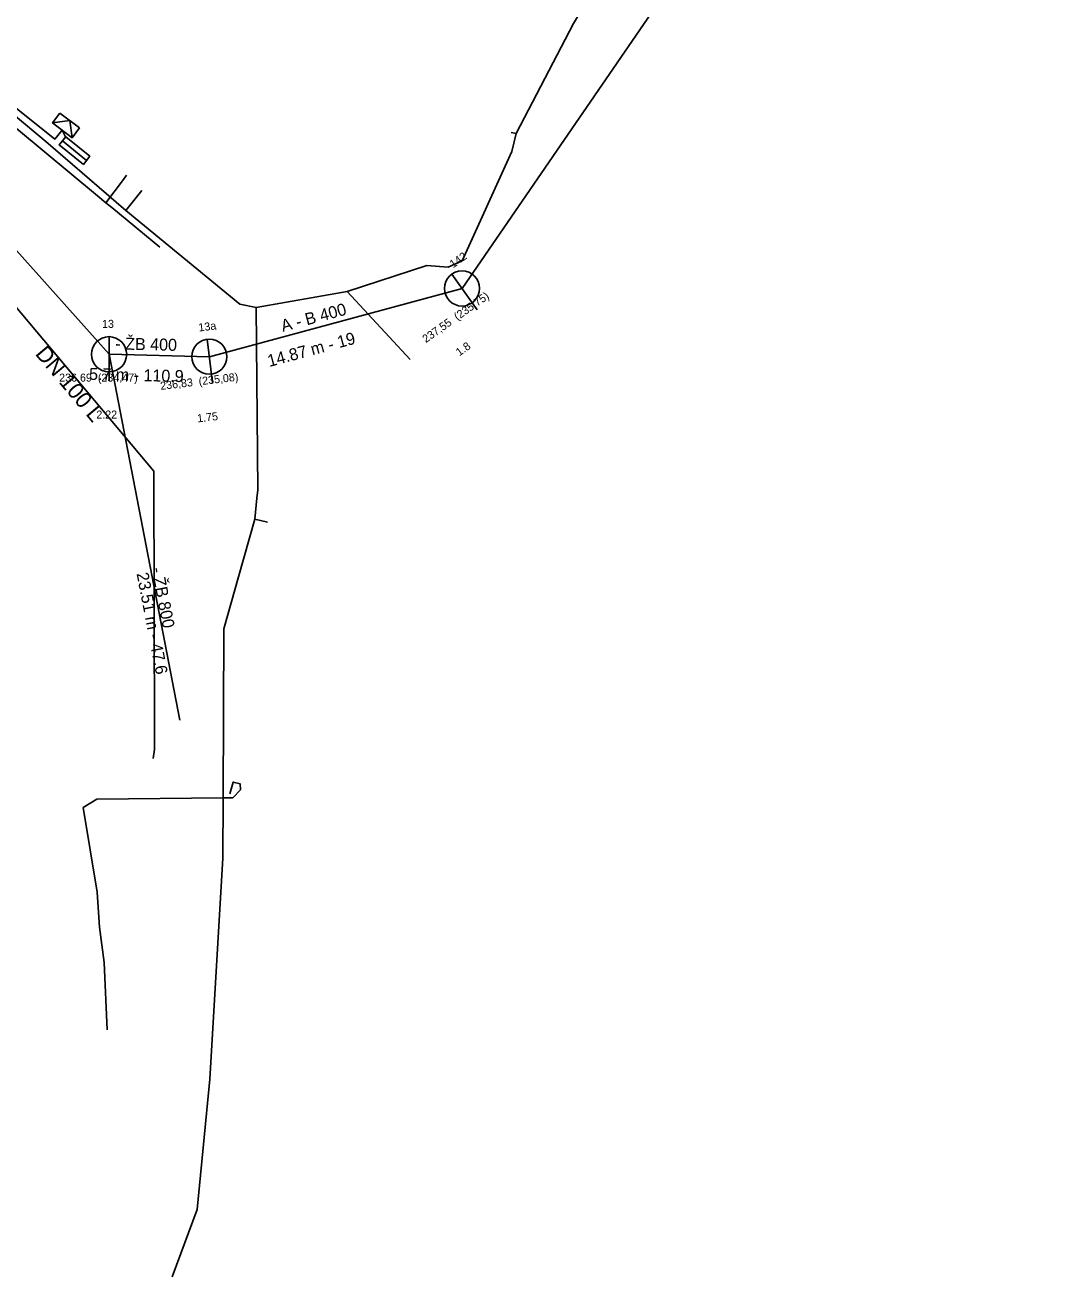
# Model space of a CAD drawing. Extents: x -600636 to -600148, y -1203980 to -1203569.
# Drawn here: x -600381.7 to -600322.7, y -1203980.3 to -1203909.2 of the extents above; entities that cross this region are included whole.
import ezdxf

# ---------------------------------------------------------------- set-up
doc = ezdxf.new("R2010")
doc.units = 0
for name, color, linetype in [('Cetin NN přípojka', 7, 'Continuous'), ('Cetin zam průběh', 7, 'Continuous'), ('EON podzemní NN', 7, 'Continuous'), ('GasNet STL', 7, 'Continuous'), ('Implicitní', 7, 'Continuous'), ('VaK Břeclav_kanalizace', 7, 'Continuous'), ('VaK Břeclav_kanalizace_popis', 7, 'Continuous'), ('Vak Břeclav_vodovod', 7, 'Continuous'), ('Vak Břeclav_vodovod_popis', 7, 'Continuous'), ('Vrstva 9', 7, 'Continuous')]:
    doc.layers.add(name, color=color, linetype=linetype)

# ---------------------------------------------------------------- blocks, each defined once
blk = doc.blocks.new('NN630')
at = {"layer": 'Vrstva 9'}
for points in [[(-0.003, -0.7), (-0.703, 0)], [(-0.703, -0.7), (-0.703, 0), (0.697, 0), (0.697, -0.7)], [(-0.703, -0.7), (0.697, -0.7)], [(-0.003, -0.7), (0.697, 0)]]:
    blk.add_lwpolyline(points, dxfattribs=at)
blk = doc.blocks.new('MoSymbol 2')
at = {"layer": 'Implicitní'}
blk.add_line((0, 0.0005), (0, -0.00075), dxfattribs=at)
blk.add_circle((0, 0), 0.0005, dxfattribs=at)

msp = doc.modelspace()

# ---------------------------------------------------------------- linework, layer by layer
at = {"layer": 'Cetin NN přípojka'}
for points in [[(-600375.93, -1203919.71), (-600380.48, -1203915.79), (-600384.28, -1203912.62)], [(-600369.45, -1203925.03), (-600375.93, -1203919.71)], [(-600368.52, -1203925.23), (-600369.45, -1203925.03)], [(-600368.6, -1203937.26), (-600368.48, -1203936.06), (-600368.43, -1203935.58), (-600368.52, -1203925.23)], [(-600373.29, -1203980.33), (-600371.87, -1203976.49), (-600371.16, -1203969.09), (-600370.42, -1203956.52), (-600370.4, -1203953.1), (-600370.36, -1203943.48), (-600369.52, -1203940.54), (-600368.6, -1203937.26)]]:
    msp.add_lwpolyline(points, dxfattribs=at)
at = {"layer": 'Cetin zam průběh'}
for points in [[(-600335.63, -1203887.95), (-600339.37, -1203893.05), (-600341.59, -1203896.64), (-600342.53, -1203897.34), (-600343.84, -1203899.03), (-600344.48, -1203900.27), (-600348.64, -1203906.02), (-600350.48, -1203909.08), (-600353.75, -1203915.34)], [(-600375.93, -1203919.71), (-600380.48, -1203915.79), (-600384.28, -1203912.62)], [(-600353.75, -1203915.34), (-600353.99, -1203916.35), (-600356.82, -1203922.57), (-600357.6, -1203922.94), (-600358.81, -1203922.84), (-600363.34, -1203924.32)], [(-600354.03, -1203915.28), (-600353.75, -1203915.34)], [(-600375.93, -1203919.71), (-600375.01, -1203918.57)], [(-600369.45, -1203925.03), (-600375.93, -1203919.71)], [(-600368.52, -1203925.23), (-600363.34, -1203924.32)], [(-600359.76, -1203928.18), (-600363.34, -1203924.32)], [(-600368.52, -1203925.23), (-600369.45, -1203925.03)], [(-600368.6, -1203937.26), (-600368.48, -1203936.06), (-600368.43, -1203935.58), (-600368.52, -1203925.23)], [(-600368.43, -1203935.58), (-600368.52, -1203925.23)], [(-600373.29, -1203980.33), (-600371.87, -1203976.49), (-600371.16, -1203969.09), (-600370.42, -1203956.52), (-600370.4, -1203953.1), (-600370.36, -1203943.48), (-600369.52, -1203940.54), (-600368.6, -1203937.26)], [(-600368.6, -1203937.26), (-600367.88, -1203937.42)], [(-600370.01, -1203952.86), (-600369.82, -1203952.2), (-600369.43, -1203952.29), (-600369.41, -1203952.64), (-600369.85, -1203953.09), (-600370.4, -1203953.1), (-600377.57, -1203953.18), (-600378.36, -1203953.65), (-600377.55, -1203958.46), (-600377.43, -1203960.44), (-600377.16, -1203962.46), (-600376.99, -1203966.29)], [(-600378.36, -1203953.65), (-600377.57, -1203953.18), (-600370.4, -1203953.1), (-600369.85, -1203953.09), (-600369.41, -1203952.64)]]:
    msp.add_lwpolyline(points, dxfattribs=at)
at = {"layer": 'EON podzemní NN'}
msp.add_lwpolyline([(-600378.16, -1203916.863), (-600379.522, -1203915.745), (-600379.349, -1203915.528), (-600379.54, -1203915.15), (-600379.957, -1203915.651), (-600387.504, -1203909.637), (-600390.807, -1203907.047), (-600391.062, -1203906.995), (-600393.313, -1203904.332), (-600393.34, -1203904.193), (-600393.41, -1203902.313), (-600393.3, -1203900.631), (-600393.268, -1203900.631)], dxfattribs=at)
msp.add_lwpolyline([(-600378.34, -1203917.104), (-600379.712, -1203915.977), (-600379.332, -1203915.513), (-600377.98, -1203916.623)], close=True, dxfattribs=at)
at = {"layer": 'GasNet STL'}
for points in [[(-600382.26, -1203914.94), (-600382.14, -1203915.04), (-600377.54, -1203918.87), (-600377.06, -1203919.27)], [(-600377.06, -1203919.27), (-600376.056, -1203917.943), (-600375.88, -1203917.71)], [(-600377.06, -1203919.27), (-600376.73, -1203919.54), (-600373.992, -1203921.797)]]:
    msp.add_lwpolyline(points, dxfattribs=at)
at = {"layer": 'VaK Břeclav_kanalizace'}
for p, q in [((-600322.72, -1203874.5), (-600356.82, -1203924.14)), ((-600376.879, -1203927.881), (-600392.69, -1203910.19)), ((-600356.82, -1203924.14), (-600371.18, -1203928.02)), ((-600372.86, -1203948.688), (-600376.879, -1203927.881)), ((-600371.18, -1203928.02), (-600376.879, -1203927.881))]:
    msp.add_line(p, q, dxfattribs=at)
at = {"layer": 'Vak Břeclav_vodovod'}
for p in [(-600374.301, -1203949.917), (-600374.371, -1203950.866)]:
    msp.add_line(p, (-600374.3, -1203950.35), dxfattribs=at)
msp.add_lwpolyline([(-600391.91, -1203913.607), (-600374.345, -1203934.519), (-600374.301, -1203949.917)], dxfattribs=at)

# ---------------------------------------------------------------- block references
at = {"layer": 'EON podzemní NN', "rotation": 142.71324171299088}
msp.add_blockref('NN630', (-600379.54, -1203915.15), dxfattribs=at)
at = {"layer": 'VaK Břeclav_kanalizace'}
for p, xscale, yscale, rotation in [((-600356.82, -1203924.14), 1999.750031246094, 1999.7500312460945, 35.31651185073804), ((-600371.18, -1203928.02), 1999.7500312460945, 1999.7500312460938, 6.841182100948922)]:
    msp.add_blockref('MoSymbol 2', p, dxfattribs=dict(at, xscale=xscale, yscale=yscale, rotation=rotation))
at = {"layer": 'VaK Břeclav_kanalizace', "xscale": 1999.750031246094, "yscale": 1999.750031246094}
msp.add_blockref('MoSymbol 2', (-600376.879, -1203927.881), dxfattribs=at)

# ---------------------------------------------------------------- texts
at = {"layer": 'VaK Břeclav_kanalizace_popis'}
for s, height, rotation, p in [('142', 0.4549, 35.31651, (-600357.324, -1203922.997)), ('237,55  (235,75)', 0.45494, 35.31651, (-600358.873, -1203927.252)), ('A - B 400', 0.6824, 15.11999, (-600367.007, -1203926.61)), ('13a', 0.4549, 6.84118, (-600371.772, -1203926.591)), ('- ŽB 400', 0.6824, 358.59872, (-600376.527, -1203927.607)), ('14.87 m - 19', 0.68241, 15.11999, (-600367.77, -1203928.605)), ('1.8', 0.4549, 35.31651, (-600356.972, -1203928.006)), ('5.7 m - 110.9', 0.68241, 358.59872, (-600378.022, -1203929.335)), ('236,83  (235,08)', 0.45494, 6.84118, (-600373.944, -1203929.91)), ('1.75', 0.4549, 6.84118, (-600371.846, -1203931.758)), ('23.51 m - 47.6', 0.68241, 280.93091, (-600375.32, -1203940.349)), ('- ŽB 800', 0.6824, 280.93091, (-600374.472, -1203940.062))]:
    msp.add_text(s, height=height, rotation=rotation, dxfattribs=at).set_placement(p)
for s, height, p in [('13', 0.4549, (-600377.28, -1203926.381)), ('236,69  (234,47)', 0.45494, (-600379.717, -1203929.436)), ('2.22', 0.4549, (-600377.605, -1203931.536))]:
    msp.add_text(s, height=height, dxfattribs=at).set_placement(p)
at = {"layer": 'Vak Břeclav_vodovod_popis'}
msp.add_text('DN 100 L', height=0.9099, rotation=310.02853, dxfattribs=at).set_placement((-600381.116, -1203927.873))

doc.saveas('drawing.dxf')
